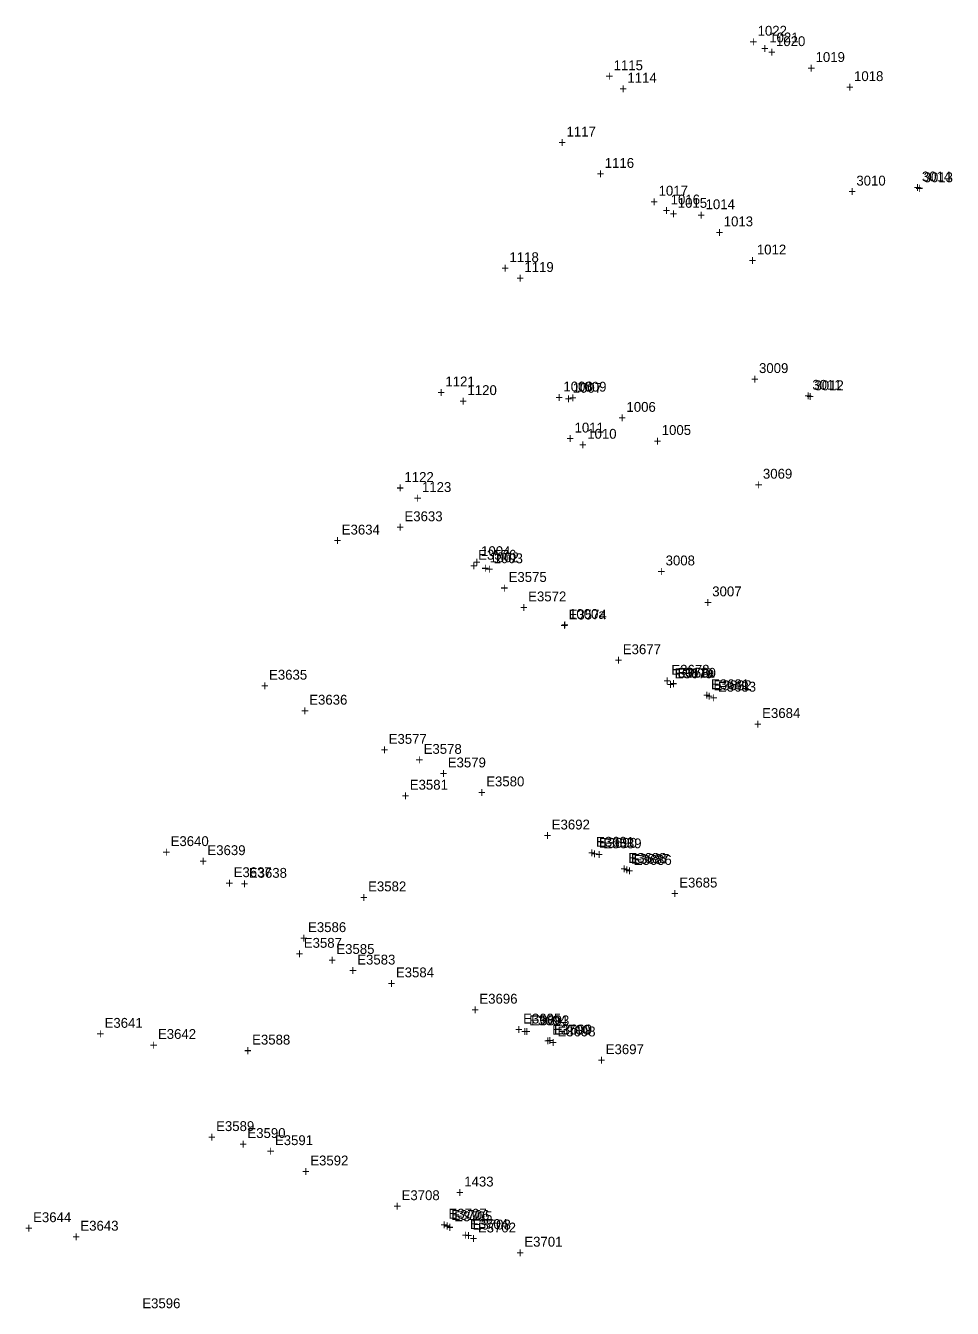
# Model space of a CAD drawing. Extents: x 1667192 to 1669644, y 336680 to 339991.
# Drawn here: x 1667364.7 to 1667599.7, y 338334.4 to 338659.5 of the extents above; entities that cross this region are included whole.
import ezdxf

# ---------------------------------------------------------------- set-up
doc = ezdxf.new("R2010")
doc.units = 0
for name, color, linetype in [('S_Curb_Type_5', 7, 'Continuous'), ('S_Drainage_CB', 7, 'Continuous'), ('S_Drainage_Ditch_Line', 7, 'Continuous'), ('S_Ground_Elevation', 7, 'Continuous'), ('S_Roadway_Centerline', 7, 'Continuous'), ('S_Roadway_Edge_Pavement', 7, 'Continuous'), ('S_Roadway_Edge_TW', 7, 'Continuous'), ('S_Traffic_Sign_DoublePost', 7, 'Continuous'), ('S_Traffic_Sign_SinglePost', 7, 'Continuous'), ('S_Trees_TreeLine', 7, 'Continuous'), ('S_Utilities_GuyWire3', 7, 'Continuous'), ('S_Utilities_Pole_Power', 7, 'Continuous'), ('S_Utilities_Pole_StreetLight', 7, 'Continuous')]:
    doc.layers.add(name, color=color, linetype=linetype)

msp = doc.modelspace()

# ---------------------------------------------------------------- texts
at = {"layer": 'S_Curb_Type_5'}
for s, p in [('3013', (1667592.37, 338619.82)), ('+', (1667590.31, 338617.07)), ('3012', (1667564.7, 338567.08)), ('+', (1667562.64, 338564.33)), ('3011a', (1667530.05, 338494.29)), ('E3680', (1667530.03, 338494.24)), ('+', (1667527.97, 338491.49)), ('+', (1667527.99, 338491.54)), ('E3681', (1667538.47, 338491.33)), ('+', (1667536.41, 338488.58)), ('E3689', (1667511.18, 338451.01)), ('+', (1667509.12, 338448.26)), ('E3688', (1667517.51, 338447.32)), ('+', (1667515.45, 338444.57)), ('E3693', (1667492.87, 338406.15)), ('+', (1667490.81, 338403.4)), ('E3700', (1667498.19, 338403.77)), ('+', (1667496.13, 338401.02)), ('E3705', (1667473.36, 338356.48)), ('E3704', (1667477.34, 338354.53)), ('+', (1667471.3, 338353.73)), ('+', (1667475.28, 338351.78))]:
    msp.add_text(s, height=2.5, dxfattribs=at).set_placement(p)
at = {"layer": 'S_Drainage_CB'}
for s, p in [('3069', (1667551.63, 338544.69)), ('+', (1667549.57, 338541.94))]:
    msp.add_text(s, height=2.5, dxfattribs=at).set_placement(p)
at = {"layer": 'S_Drainage_Ditch_Line'}
for s, p in [('1021', (1667553.23, 338655.26)), ('+', (1667551.17, 338652.51)), ('1016', (1667528.24, 338614.19)), ('+', (1667526.18, 338611.44)), ('1007', (1667503.4, 338566.46)), ('+', (1667501.34, 338563.71)), ('1002', (1667482.33, 338523.51)), ('+', (1667480.27, 338520.76))]:
    msp.add_text(s, height=2.5, dxfattribs=at).set_placement(p)
at = {"layer": 'S_Ground_Elevation'}
for s, p in [('1022', (1667550.28, 338656.97)), ('+', (1667548.22, 338654.22)), ('1020', (1667554.94, 338654.32)), ('+', (1667552.88, 338651.57)), ('1114', (1667517.27, 338645.06)), ('+', (1667515.21, 338642.31)), ('1017', (1667525.17, 338616.43)), ('+', (1667523.11, 338613.68)), ('1015', (1667530.04, 338613.34)), ('+', (1667527.98, 338610.59)), ('1119', (1667491.14, 338597.08)), ('+', (1667489.08, 338594.33)), ('1120', (1667476.72, 338565.88)), ('1008', (1667501.04, 338566.8)), ('1009', (1667504.52, 338566.75)), ('+', (1667474.66, 338563.13)), ('+', (1667498.98, 338564.05)), ('+', (1667502.46, 338564)), ('1123', (1667465.18, 338541.31)), ('+', (1667463.12, 338538.56)), ('E3633', (1667460.74, 338533.91)), ('E3634', (1667444.84, 338530.53)), ('+', (1667458.68, 338531.16)), ('+', (1667442.77, 338527.78)), ('E3576', (1667479.43, 338524.15)), ('1004', (1667480.17, 338525.07)), ('1003', (1667483.34, 338523.26)), ('+', (1667477.37, 338521.4)), ('+', (1667478.11, 338522.32)), ('+', (1667481.28, 338520.51)), ('E3575', (1667487.15, 338518.52)), ('+', (1667485.09, 338515.77)), ('E3635', (1667426.41, 338493.74)), ('+', (1667424.35, 338490.99)), ('E3636', (1667436.6, 338487.41)), ('+', (1667434.54, 338484.66)), ('E3577', (1667456.74, 338477.49)), ('E3578', (1667465.6, 338474.95)), ('+', (1667454.68, 338474.74)), ('+', (1667463.53, 338472.2)), ('E3640', (1667401.45, 338451.57)), ('+', (1667399.39, 338448.82)), ('E3637', (1667417.43, 338443.7)), ('+', (1667415.37, 338440.95)), ('E3586', (1667436.3, 338429.77)), ('+', (1667434.24, 338427.02)), ('E3587', (1667435.22, 338425.79)), ('+', (1667433.16, 338423.04)), ('E3585', (1667443.47, 338424.23)), ('+', (1667441.41, 338421.48)), ('E3641', (1667384.71, 338405.51)), ('+', (1667382.65, 338402.76)), ('E3642', (1667398.24, 338402.69)), ('E3588', (1667422.12, 338401.26)), ('+', (1667396.18, 338399.94)), ('+', (1667420.06, 338398.51)), ('E3589', (1667412.99, 338379.34)), ('E3590', (1667420.92, 338377.59)), ('+', (1667410.93, 338376.59)), ('+', (1667418.86, 338374.84)), ('E3644', (1667366.59, 338356.25)), ('E3643', (1667378.57, 338354.09)), ('+', (1667364.53, 338353.5)), ('+', (1667376.51, 338351.34)), ('E3596', (1667394.27, 338334.44))]:
    msp.add_text(s, height=2.5, dxfattribs=at).set_placement(p)
at = {"layer": 'S_Roadway_Centerline'}
for s, p in [('3010', (1667575.32, 338618.98)), ('+', (1667573.26, 338616.23)), ('3009', (1667550.64, 338571.46)), ('+', (1667548.57, 338568.71)), ('3008', (1667526.96, 338522.71)), ('+', (1667524.9, 338519.97))]:
    msp.add_text(s, height=2.5, dxfattribs=at).set_placement(p)
at = {"layer": 'S_Roadway_Edge_Pavement'}
for s, p in [('1019', (1667564.98, 338650.3)), ('+', (1667562.92, 338647.55)), ('3014', (1667591.93, 338620.03)), ('+', (1667589.87, 338617.28)), ('1013', (1667541.69, 338608.65)), ('+', (1667539.63, 338605.9)), ('3011', (1667564.16, 338567.23)), ('+', (1667562.1, 338564.48)), ('1006', (1667517.03, 338561.63)), ('+', (1667514.97, 338558.88)), ('E3572', (1667492.11, 338513.59)), ('3007', (1667538.78, 338514.87)), ('+', (1667490.05, 338510.84)), ('+', (1667536.72, 338512.12)), ('E3679', (1667529.26, 338494.1)), ('+', (1667527.19, 338491.35)), ('E3682', (1667539.08, 338491.08)), ('+', (1667537.02, 338488.33)), ('E3579', (1667471.72, 338471.51)), ('+', (1667469.66, 338468.76)), ('E3690', (1667510.03, 338451.14)), ('+', (1667507.97, 338448.39)), ('E3687', (1667518.19, 338447.08)), ('+', (1667516.13, 338444.33)), ('E3583', (1667448.77, 338421.55)), ('+', (1667446.71, 338418.8)), ('E3694', (1667492.36, 338406.15)), ('+', (1667490.3, 338403.4)), ('E3699', (1667498.65, 338403.83)), ('+', (1667496.59, 338401.08)), ('E3591', (1667427.9, 338375.78)), ('+', (1667425.84, 338373.03)), ('1433', (1667475.9, 338365.29)), ('+', (1667473.83, 338362.54)), ('E3706', (1667472.62, 338356.82)), ('E3703', (1667478.05, 338354.39)), ('+', (1667470.56, 338354.07)), ('+', (1667475.99, 338351.64))]:
    msp.add_text(s, height=2.5, dxfattribs=at).set_placement(p)
at = {"layer": 'S_Roadway_Edge_TW'}
for s, p in [('1018', (1667574.73, 338645.46)), ('+', (1667572.67, 338642.71)), ('1012', (1667550.09, 338601.51)), ('+', (1667548.03, 338598.76)), ('1005', (1667525.97, 338555.77)), ('+', (1667523.91, 338553.02)), ('E3574', (1667502.36, 338509)), ('1000a', (1667502.47, 338509.15)), ('+', (1667500.3, 338506.25)), ('+', (1667500.41, 338506.4)), ('E3677', (1667516.1, 338500.21)), ('+', (1667514.04, 338497.46)), ('E3678', (1667528.42, 338495)), ('+', (1667526.36, 338492.25)), ('E3683', (1667540.22, 338490.71)), ('+', (1667538.16, 338487.96)), ('+', (1667549.38, 338481.28)), ('E3684', (1667551.44, 338484.03)), ('E3580', (1667481.47, 338466.71)), ('+', (1667479.41, 338463.96)), ('E3692', (1667498.08, 338455.78)), ('+', (1667496.02, 338453.03)), ('E3691', (1667509.32, 338451.41)), ('+', (1667507.26, 338448.66)), ('E3686', (1667518.85, 338446.8)), ('+', (1667516.79, 338444.05)), ('E3685', (1667530.41, 338441.07)), ('+', (1667528.34, 338438.32)), ('E3584', (1667458.57, 338418.3)), ('+', (1667456.51, 338415.55)), ('E3696', (1667479.74, 338411.63)), ('+', (1667477.68, 338408.88)), ('E3695', (1667490.82, 338406.6)), ('+', (1667488.76, 338403.85)), ('E3698', (1667499.53, 338403.33)), ('+', (1667497.47, 338400.58)), ('E3697', (1667511.77, 338398.83)), ('+', (1667509.71, 338396.08)), ('E3592', (1667436.86, 338370.63)), ('+', (1667434.79, 338367.88)), ('E3708', (1667460.01, 338361.83)), ('+', (1667457.95, 338359.08)), ('E3707', (1667471.91, 338357.15)), ('+', (1667469.85, 338354.4)), ('E3702', (1667479.36, 338353.64)), ('+', (1667477.29, 338350.89)), ('E3701', (1667491.14, 338350.05)), ('+', (1667489.08, 338347.3))]:
    msp.add_text(s, height=2.5, dxfattribs=at).set_placement(p)
at = {"layer": 'S_Traffic_Sign_DoublePost'}
for s, p in [('1011', (1667503.87, 338556.38)), ('+', (1667501.81, 338553.63)), ('1010', (1667507.08, 338554.81)), ('+', (1667505.02, 338552.06))]:
    msp.add_text(s, height=2.5, dxfattribs=at).set_placement(p)
at = {"layer": 'S_Traffic_Sign_SinglePost'}
for s, p in [('E3582', (1667451.53, 338440.1)), ('+', (1667449.47, 338437.35))]:
    msp.add_text(s, height=2.5, dxfattribs=at).set_placement(p)
at = {"layer": 'S_Trees_TreeLine'}
for s, p in [('1115', (1667513.77, 338648.21)), ('+', (1667511.71, 338645.46)), ('1118', (1667487.37, 338599.57)), ('+', (1667485.31, 338596.82)), ('1121', (1667471.12, 338568.07)), ('+', (1667469.06, 338565.32)), ('1122', (1667460.74, 338543.87)), ('+', (1667458.68, 338541.12))]:
    msp.add_text(s, height=2.5, dxfattribs=at).set_placement(p)
at = {"layer": 'S_Utilities_GuyWire3'}
for s, p in [('1117', (1667501.83, 338631.4)), ('+', (1667499.77, 338628.65)), ('E3639', (1667410.78, 338449.28)), ('+', (1667408.72, 338446.53))]:
    msp.add_text(s, height=2.5, dxfattribs=at).set_placement(p)
at = {"layer": 'S_Utilities_Pole_Power'}
for s, p in [('1116', (1667511.53, 338623.46)), ('+', (1667509.47, 338620.71)), ('E3638', (1667421.28, 338443.53)), ('+', (1667419.22, 338440.78))]:
    msp.add_text(s, height=2.5, dxfattribs=at).set_placement(p)
at = {"layer": 'S_Utilities_Pole_StreetLight'}
for s, p in [('1014', (1667537.09, 338612.99)), ('+', (1667535.02, 338610.24)), ('E3581', (1667462.09, 338465.87)), ('+', (1667460.03, 338463.12))]:
    msp.add_text(s, height=2.5, dxfattribs=at).set_placement(p)

doc.saveas('drawing.dxf')
